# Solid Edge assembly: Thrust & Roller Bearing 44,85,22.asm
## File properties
Title: Thrust & Roller Bearing 44,85,22
Author: Dan
Template: Normal.asm
Last saved by: Dan
Revision: 97
Application: Solid Edge
Document Number: P52-004
Project Name: Piston Pump P52
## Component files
Bearing Housing.asm
Thrust Cage.asm
Thrust Washer.par
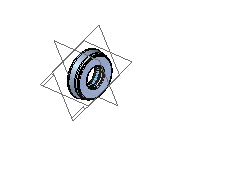
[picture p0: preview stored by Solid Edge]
